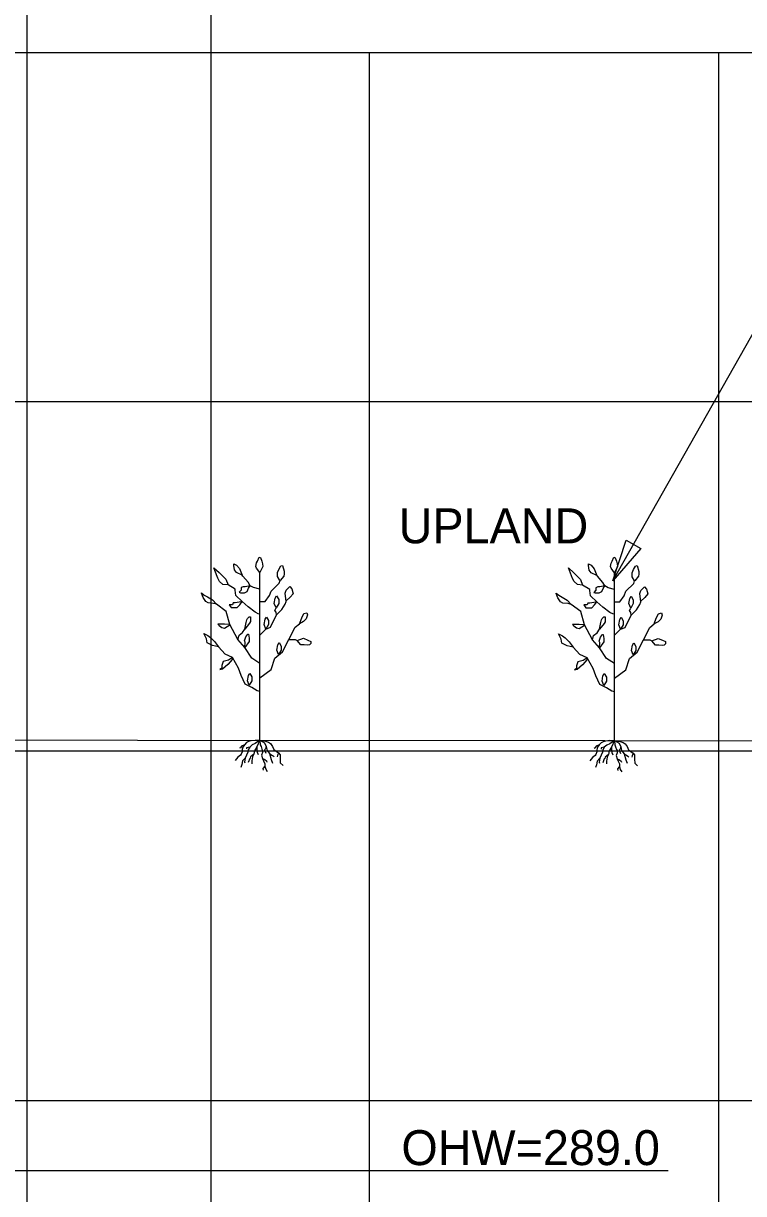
# Model space of a CAD drawing. Extents: x 1578769 to 1579225, y 724002 to 724828.
# Drawn here: x 1578825.08 to 1578835.39, y 724400.81 to 724417.56 of the extents above; entities that cross this region are included whole.
import ezdxf

# ---------------------------------------------------------------- set-up
doc = ezdxf.new("R2010")
doc.units = 0
for name, color, linetype in [('1', 7, 'Continuous'), ('Default', 7, 'Continuous'), ('Old_Level_1', 7, 'Continuous'), ('Old_Level_41', 7, 'Continuous'), ('R_Exist Surface', 7, 'Continuous')]:
    doc.layers.add(name, color=color, linetype=linetype)

msp = doc.modelspace()

# ---------------------------------------------------------------- linework, layer by layer
at = {"layer": '1'}
for p, q in [((1578828.465, 724407.303), (1578828.465, 724409.703)), ((1578833.539, 724407.3), (1578833.539, 724409.7)), ((1578828.47, 724407.298), (1578828.472, 724407.302)), ((1578833.544, 724407.295), (1578833.546, 724407.299)), ((1578820.032, 724401.146), (1578834.308, 724401.146))]:
    msp.add_line(p, q, dxfattribs=at)
for points in [[(1578833.517, 724409.582), (1578835.732, 724413.491), (1578836.418, 724413.491)], [(1578828.752, 724409.589), (1578828.721, 724409.646), (1578828.721, 724409.703), (1578828.74, 724409.747), (1578828.765, 724409.797), (1578828.79, 724409.804), (1578828.815, 724409.722), (1578828.815, 724409.684), (1578828.809, 724409.652), (1578828.759, 724409.589)], [(1578833.826, 724409.586), (1578833.795, 724409.643), (1578833.795, 724409.7), (1578833.814, 724409.744), (1578833.839, 724409.794), (1578833.864, 724409.801), (1578833.889, 724409.719), (1578833.889, 724409.681), (1578833.883, 724409.649), (1578833.833, 724409.586)], [(1578828.465, 724409.463), (1578828.377, 724409.488), (1578828.326, 724409.513), (1578828.301, 724409.564), (1578828.225, 724409.652), (1578828.213, 724409.665)], [(1578828.465, 724409.286), (1578828.541, 724409.286), (1578828.604, 724409.374), (1578828.629, 724409.437), (1578828.743, 724409.551), (1578828.755, 724409.589)], [(1578833.539, 724409.46), (1578833.451, 724409.485), (1578833.4, 724409.51), (1578833.375, 724409.561), (1578833.299, 724409.649), (1578833.287, 724409.662)], [(1578833.539, 724409.283), (1578833.615, 724409.283), (1578833.678, 724409.371), (1578833.703, 724409.434), (1578833.817, 724409.548), (1578833.829, 724409.586)], [(1578827.847, 724409.248), (1578827.803, 724409.261), (1578827.727, 724409.267), (1578827.695, 724409.286), (1578827.657, 724409.343), (1578827.632, 724409.406), (1578827.632, 724409.412), (1578827.67, 724409.381), (1578827.72, 724409.355), (1578827.79, 724409.311), (1578827.847, 724409.248)], [(1578828.453, 724409.109), (1578828.402, 724409.134), (1578828.301, 724409.21), (1578828.213, 724409.286), (1578828.124, 724409.374), (1578828.112, 724409.45), (1578828.112, 724409.463), (1578828.011, 724409.526)], [(1578828.699, 724409.197), (1578828.673, 724409.261), (1578828.686, 724409.336), (1578828.705, 724409.368), (1578828.737, 724409.317), (1578828.737, 724409.261), (1578828.699, 724409.197)], [(1578828.844, 724409.286), (1578828.831, 724409.406), (1578828.844, 724409.45), (1578828.894, 724409.501), (1578828.926, 724409.469), (1578828.945, 724409.4), (1578828.901, 724409.349), (1578828.844, 724409.298)], [(1578832.921, 724409.245), (1578832.876, 724409.258), (1578832.801, 724409.264), (1578832.769, 724409.283), (1578832.731, 724409.34), (1578832.706, 724409.403), (1578832.706, 724409.409), (1578832.744, 724409.378), (1578832.794, 724409.352), (1578832.864, 724409.308), (1578832.921, 724409.245)], [(1578833.526, 724409.106), (1578833.476, 724409.131), (1578833.375, 724409.207), (1578833.287, 724409.283), (1578833.198, 724409.371), (1578833.186, 724409.447), (1578833.186, 724409.46), (1578833.085, 724409.523)], [(1578833.773, 724409.194), (1578833.747, 724409.258), (1578833.76, 724409.333), (1578833.779, 724409.365), (1578833.81, 724409.314), (1578833.81, 724409.258), (1578833.773, 724409.194)], [(1578833.918, 724409.283), (1578833.905, 724409.403), (1578833.918, 724409.447), (1578833.968, 724409.498), (1578834, 724409.466), (1578834.019, 724409.397), (1578833.975, 724409.346), (1578833.918, 724409.295)], [(1578828.465, 724408.402), (1578828.352, 724408.477), (1578828.251, 724408.629), (1578828.15, 724408.743), (1578828.036, 724408.957), (1578827.986, 724409.147), (1578827.847, 724409.248)], [(1578828.465, 724408.818), (1578828.478, 724408.818), (1578828.554, 724408.894), (1578828.617, 724408.919), (1578828.705, 724409.096), (1578828.781, 724409.172), (1578828.831, 724409.248), (1578828.844, 724409.286)], [(1578828.705, 724409.096), (1578828.699, 724409.134), (1578828.68, 724409.159), (1578828.699, 724409.197)], [(1578833.539, 724408.399), (1578833.425, 724408.474), (1578833.324, 724408.626), (1578833.224, 724408.74), (1578833.11, 724408.954), (1578833.059, 724409.144), (1578832.921, 724409.245)], [(1578833.539, 724408.815), (1578833.552, 724408.815), (1578833.627, 724408.891), (1578833.691, 724408.917), (1578833.779, 724409.093), (1578833.855, 724409.169), (1578833.905, 724409.245), (1578833.918, 724409.283)], [(1578833.779, 724409.093), (1578833.773, 724409.131), (1578833.754, 724409.157), (1578833.773, 724409.194)], [(1578828.554, 724408.894), (1578828.528, 724408.957), (1578828.541, 724409.033), (1578828.56, 724409.065), (1578828.591, 724409.014), (1578828.591, 724408.957), (1578828.554, 724408.894)], [(1578829.033, 724408.97), (1578829.065, 724409.052), (1578829.096, 724409.115), (1578829.14, 724409.128), (1578829.147, 724409.096), (1578829.128, 724409.04), (1578829.09, 724409.002), (1578829.033, 724408.97)], [(1578833.627, 724408.891), (1578833.602, 724408.954), (1578833.615, 724409.03), (1578833.634, 724409.062), (1578833.665, 724409.011), (1578833.665, 724408.954), (1578833.627, 724408.891)], [(1578834.107, 724408.967), (1578834.139, 724409.049), (1578834.17, 724409.112), (1578834.214, 724409.125), (1578834.221, 724409.093), (1578834.202, 724409.037), (1578834.164, 724408.999), (1578834.107, 724408.967)], [(1578828.036, 724408.957), (1578827.962, 724408.964), (1578827.905, 724408.964), (1578827.866, 724408.964), (1578827.885, 724408.944), (1578827.924, 724408.916), (1578827.962, 724408.906), (1578828.038, 724408.954)], [(1578828.15, 724408.743), (1578828.169, 724408.806), (1578828.219, 724408.844), (1578828.251, 724408.894)], [(1578828.465, 724408.194), (1578828.629, 724408.313), (1578828.68, 724408.477), (1578828.793, 724408.566), (1578828.882, 724408.743), (1578828.97, 724408.919), (1578829.033, 724408.97)], [(1578833.11, 724408.954), (1578833.036, 724408.961), (1578832.978, 724408.961), (1578832.94, 724408.961), (1578832.959, 724408.941), (1578832.998, 724408.913), (1578833.036, 724408.903), (1578833.112, 724408.951)], [(1578833.224, 724408.74), (1578833.242, 724408.803), (1578833.293, 724408.841), (1578833.325, 724408.891)], [(1578833.539, 724408.191), (1578833.703, 724408.31), (1578833.754, 724408.474), (1578833.867, 724408.563), (1578833.956, 724408.74), (1578834.044, 724408.917), (1578834.107, 724408.967)], [(1578828.734, 724408.529), (1578828.709, 724408.592), (1578828.722, 724408.668), (1578828.741, 724408.699), (1578828.772, 724408.649), (1578828.772, 724408.592), (1578828.734, 724408.529)], [(1578828.882, 724408.743), (1578828.945, 724408.743), (1578828.97, 724408.743), (1578829.002, 724408.73)], [(1578829.002, 724408.73), (1578829.09, 724408.762), (1578829.153, 724408.736), (1578829.197, 724408.717), (1578829.197, 724408.686), (1578829.178, 724408.667), (1578829.147, 724408.661), (1578829.103, 724408.667), (1578829.052, 724408.667), (1578829.002, 724408.73)], [(1578833.808, 724408.526), (1578833.783, 724408.589), (1578833.796, 724408.665), (1578833.815, 724408.696), (1578833.846, 724408.646), (1578833.846, 724408.589), (1578833.808, 724408.526)], [(1578833.956, 724408.74), (1578834.019, 724408.74), (1578834.044, 724408.74), (1578834.076, 724408.727)], [(1578834.076, 724408.727), (1578834.164, 724408.759), (1578834.227, 724408.733), (1578834.271, 724408.714), (1578834.271, 724408.683), (1578834.252, 724408.664), (1578834.221, 724408.658), (1578834.177, 724408.664), (1578834.126, 724408.664), (1578834.076, 724408.727)], [(1578828.468, 724407.999), (1578828.43, 724408.008), (1578828.353, 724408.056), (1578828.258, 724408.104), (1578828.2, 724408.228), (1578828.162, 724408.333), (1578828.076, 724408.486), (1578827.971, 724408.534), (1578827.876, 724408.639), (1578827.876, 724408.639)], [(1578833.542, 724407.996), (1578833.504, 724408.005), (1578833.427, 724408.053), (1578833.332, 724408.101), (1578833.274, 724408.225), (1578833.236, 724408.33), (1578833.15, 724408.483), (1578833.045, 724408.531), (1578832.95, 724408.636), (1578832.95, 724408.636)], [(1578828.314, 724408.089), (1578828.289, 724408.152), (1578828.302, 724408.228), (1578828.321, 724408.26), (1578828.352, 724408.209), (1578828.352, 724408.152), (1578828.314, 724408.089)], [(1578833.388, 724408.086), (1578833.363, 724408.149), (1578833.376, 724408.225), (1578833.395, 724408.257), (1578833.426, 724408.206), (1578833.426, 724408.149), (1578833.388, 724408.086)], [(1578828.465, 724407.303), (1578828.414, 724407.297), (1578828.398, 724407.301), (1578828.34, 724407.293), (1578828.305, 724407.285), (1578828.278, 724407.27), (1578828.247, 724407.239), (1578828.224, 724407.204), (1578828.216, 724407.169), (1578828.216, 724407.138), (1578828.2, 724407.103), (1578828.189, 724407.087), (1578828.15, 724407.06), (1578828.115, 724407.013)], [(1578828.247, 724407.239), (1578828.204, 724407.219), (1578828.189, 724407.196), (1578828.177, 724407.188)], [(1578828.465, 724407.303), (1578828.398, 724407.254), (1578828.359, 724407.235), (1578828.321, 724407.204), (1578828.301, 724407.165), (1578828.293, 724407.134), (1578828.255, 724407.048), (1578828.22, 724407.006), (1578828.208, 724406.955), (1578828.193, 724406.913)], [(1578828.321, 724407.204), (1578828.278, 724407.196), (1578828.274, 724407.18)], [(1578828.465, 724407.303), (1578828.425, 724407.208), (1578828.39, 724407.153), (1578828.379, 724407.103), (1578828.363, 724407.064), (1578828.352, 724407.006), (1578828.352, 724406.967)], [(1578828.425, 724407.208), (1578828.425, 724407.153), (1578828.429, 724407.13), (1578828.441, 724407.099)], [(1578828.465, 724407.303), (1578828.549, 724407.287), (1578828.592, 724407.274), (1578828.619, 724407.254), (1578828.646, 724407.215), (1578828.666, 724407.169), (1578828.732, 724407.122), (1578828.755, 724407.095), (1578828.755, 724407.037), (1578828.759, 724406.979), (1578828.798, 724406.94)], [(1578828.465, 724407.303), (1578828.534, 724407.266), (1578828.557, 724407.211), (1578828.569, 724407.157), (1578828.604, 724407.111), (1578828.627, 724407.025), (1578828.65, 724406.975)], [(1578828.465, 724407.303), (1578828.472, 724407.239), (1578828.484, 724407.211), (1578828.495, 724407.173), (1578828.503, 724407.157), (1578828.503, 724407.126), (1578828.491, 724407.087), (1578828.503, 724407.041), (1578828.518, 724407.006), (1578828.538, 724406.967), (1578828.538, 724406.932), (1578828.55, 724406.889), (1578828.573, 724406.854)], [(1578828.557, 724407.211), (1578828.546, 724407.18), (1578828.534, 724407.165), (1578828.553, 724407.118)], [(1578833.539, 724407.3), (1578833.488, 724407.294), (1578833.472, 724407.298), (1578833.414, 724407.29), (1578833.379, 724407.282), (1578833.352, 724407.267), (1578833.321, 724407.236), (1578833.298, 724407.201), (1578833.29, 724407.166), (1578833.29, 724407.135), (1578833.274, 724407.1), (1578833.263, 724407.084), (1578833.224, 724407.057), (1578833.189, 724407.01)], [(1578833.321, 724407.236), (1578833.278, 724407.216), (1578833.263, 724407.193), (1578833.251, 724407.185)], [(1578833.539, 724407.3), (1578833.472, 724407.251), (1578833.433, 724407.232), (1578833.395, 724407.201), (1578833.375, 724407.162), (1578833.367, 724407.131), (1578833.329, 724407.045), (1578833.294, 724407.003), (1578833.282, 724406.952), (1578833.267, 724406.91)], [(1578833.395, 724407.201), (1578833.352, 724407.193), (1578833.348, 724407.177)], [(1578833.539, 724407.3), (1578833.499, 724407.205), (1578833.464, 724407.15), (1578833.453, 724407.1), (1578833.437, 724407.061), (1578833.426, 724407.003), (1578833.426, 724406.964)], [(1578833.499, 724407.205), (1578833.499, 724407.15), (1578833.503, 724407.127), (1578833.515, 724407.096)], [(1578833.539, 724407.3), (1578833.623, 724407.284), (1578833.666, 724407.271), (1578833.693, 724407.251), (1578833.72, 724407.212), (1578833.74, 724407.166), (1578833.806, 724407.119), (1578833.829, 724407.092), (1578833.829, 724407.034), (1578833.833, 724406.976), (1578833.872, 724406.937)], [(1578833.539, 724407.3), (1578833.608, 724407.263), (1578833.631, 724407.208), (1578833.643, 724407.154), (1578833.678, 724407.108), (1578833.701, 724407.022), (1578833.724, 724406.972)], [(1578833.539, 724407.3), (1578833.546, 724407.236), (1578833.557, 724407.208), (1578833.569, 724407.17), (1578833.577, 724407.154), (1578833.577, 724407.123), (1578833.565, 724407.084), (1578833.577, 724407.038), (1578833.592, 724407.003), (1578833.612, 724406.964), (1578833.612, 724406.929), (1578833.623, 724406.886), (1578833.647, 724406.851)], [(1578833.631, 724407.208), (1578833.62, 724407.177), (1578833.608, 724407.162), (1578833.627, 724407.115)], [(1578828.255, 724407.048), (1578828.247, 724406.994), (1578828.251, 724406.979)], [(1578828.379, 724407.103), (1578828.332, 724407.064), (1578828.328, 724407.045), (1578828.321, 724407.041), (1578828.301, 724406.982)], [(1578828.503, 724407.041), (1578828.538, 724407.025), (1578828.561, 724407.006), (1578828.565, 724406.99)], [(1578828.604, 724407.111), (1578828.639, 724407.091), (1578828.658, 724407.079), (1578828.67, 724407.068)], [(1578828.732, 724407.122), (1578828.72, 724407.083), (1578828.716, 724407.064)], [(1578833.329, 724407.045), (1578833.321, 724406.991), (1578833.325, 724406.976)], [(1578833.453, 724407.1), (1578833.406, 724407.061), (1578833.402, 724407.042), (1578833.395, 724407.038), (1578833.375, 724406.979)], [(1578833.577, 724407.038), (1578833.612, 724407.022), (1578833.635, 724407.003), (1578833.639, 724406.987)], [(1578833.678, 724407.108), (1578833.713, 724407.088), (1578833.732, 724407.076), (1578833.744, 724407.065)], [(1578833.806, 724407.119), (1578833.794, 724407.08), (1578833.79, 724407.061)], [(1578828.538, 724406.932), (1578828.511, 724406.897), (1578828.515, 724406.874)], [(1578833.612, 724406.929), (1578833.585, 724406.894), (1578833.589, 724406.871)]]:
    msp.add_lwpolyline(points, dxfattribs=at)
for points in [[(1578833.917, 724410.045), (1578833.517, 724409.582), (1578833.708, 724410.164)], [(1578828.465, 724409.703), (1578828.421, 724409.766), (1578828.408, 724409.791), (1578828.421, 724409.842), (1578828.434, 724409.867), (1578828.459, 724409.924), (1578828.478, 724409.917), (1578828.497, 724409.867), (1578828.503, 724409.829), (1578828.509, 724409.791)], [(1578833.539, 724409.7), (1578833.495, 724409.763), (1578833.482, 724409.788), (1578833.495, 724409.839), (1578833.508, 724409.864), (1578833.533, 724409.921), (1578833.552, 724409.914), (1578833.571, 724409.864), (1578833.577, 724409.826), (1578833.583, 724409.788)], [(1578828.011, 724409.526), (1578827.935, 724409.532), (1578827.891, 724409.576), (1578827.866, 724409.621), (1578827.821, 724409.734), (1578827.809, 724409.772), (1578827.885, 724409.703), (1578827.929, 724409.658), (1578827.979, 724409.608)], [(1578828.213, 724409.665), (1578828.131, 724409.703), (1578828.105, 724409.741), (1578828.093, 724409.804), (1578828.093, 724409.829), (1578828.131, 724409.81), (1578828.175, 724409.76)], [(1578833.085, 724409.523), (1578833.009, 724409.529), (1578832.965, 724409.573), (1578832.94, 724409.618), (1578832.895, 724409.731), (1578832.883, 724409.769), (1578832.958, 724409.7), (1578833.003, 724409.655), (1578833.053, 724409.605)], [(1578833.287, 724409.662), (1578833.205, 724409.7), (1578833.179, 724409.738), (1578833.167, 724409.801), (1578833.167, 724409.826), (1578833.205, 724409.807), (1578833.249, 724409.757)], [(1578828.326, 724409.513), (1578828.258, 724409.499), (1578828.229, 724409.499), (1578828.2, 724409.489), (1578828.2, 724409.451), (1578828.172, 724409.422), (1578828.191, 724409.413), (1578828.248, 724409.413), (1578828.286, 724409.432), (1578828.305, 724409.479)], [(1578833.4, 724409.51), (1578833.332, 724409.496), (1578833.303, 724409.496), (1578833.274, 724409.486), (1578833.274, 724409.448), (1578833.246, 724409.419), (1578833.265, 724409.41), (1578833.322, 724409.41), (1578833.36, 724409.429), (1578833.379, 724409.476)], [(1578828.213, 724409.286), (1578828.172, 724409.279), (1578828.115, 724409.269), (1578828.086, 724409.269), (1578828.076, 724409.241), (1578828.029, 724409.241), (1578828.057, 724409.202), (1578828.095, 724409.202), (1578828.143, 724409.202), (1578828.181, 724409.241)], [(1578833.287, 724409.283), (1578833.246, 724409.276), (1578833.188, 724409.266), (1578833.16, 724409.266), (1578833.15, 724409.238), (1578833.103, 724409.238), (1578833.131, 724409.199), (1578833.169, 724409.199), (1578833.217, 724409.199), (1578833.255, 724409.238)], [(1578828.251, 724408.894), (1578828.27, 724408.989), (1578828.282, 724409.027), (1578828.288, 724409.046), (1578828.314, 724409.071), (1578828.333, 724409.071), (1578828.333, 724409.002), (1578828.32, 724408.976)], [(1578833.325, 724408.891), (1578833.343, 724408.986), (1578833.356, 724409.024), (1578833.362, 724409.043), (1578833.388, 724409.068), (1578833.407, 724409.068), (1578833.407, 724408.999), (1578833.394, 724408.973)], [(1578827.876, 724408.639), (1578827.79, 724408.658), (1578827.714, 724408.696), (1578827.704, 724408.753), (1578827.666, 724408.83), (1578827.723, 724408.801), (1578827.761, 724408.772), (1578827.819, 724408.715), (1578827.847, 724408.677)], [(1578828.251, 724408.629), (1578828.258, 724408.706), (1578828.248, 724408.725), (1578828.267, 724408.782), (1578828.296, 724408.82), (1578828.305, 724408.82), (1578828.315, 724408.763), (1578828.315, 724408.715)], [(1578832.95, 724408.636), (1578832.864, 724408.655), (1578832.788, 724408.693), (1578832.778, 724408.75), (1578832.74, 724408.827), (1578832.797, 724408.798), (1578832.835, 724408.769), (1578832.893, 724408.712), (1578832.921, 724408.674)], [(1578833.324, 724408.626), (1578833.332, 724408.703), (1578833.322, 724408.722), (1578833.341, 724408.779), (1578833.37, 724408.817), (1578833.379, 724408.817), (1578833.389, 724408.76), (1578833.389, 724408.712)], [(1578828.076, 724408.486), (1578828.019, 724408.448), (1578827.943, 724408.429), (1578827.924, 724408.371), (1578827.924, 724408.333), (1578827.895, 724408.314), (1578827.933, 724408.323), (1578828.01, 724408.39), (1578828.019, 724408.39), (1578828.076, 724408.457)], [(1578833.15, 724408.483), (1578833.093, 724408.445), (1578833.017, 724408.426), (1578832.998, 724408.368), (1578832.998, 724408.33), (1578832.969, 724408.311), (1578833.007, 724408.32), (1578833.083, 724408.387), (1578833.093, 724408.387), (1578833.15, 724408.454)]]:
    msp.add_lwpolyline(points, close=True, dxfattribs=at)
at = {"layer": 'Default'}
for p, q in [((1578827.766, 724526.976), (1578827.766, 724276.976)), ((1578825.136, 724252.141), (1578825.136, 724502.141))]:
    msp.add_line(p, q, dxfattribs=at)
at = {"layer": 'Old_Level_1'}
msp.add_lwpolyline([(1578820.032, 724417.146), (1578940.032, 724417.146), (1578940.032, 724387.146), (1578820.032, 724387.146)], dxfattribs=at)
at = {"layer": 'Old_Level_41'}
for p, q in [((1578830.032, 724417.146), (1578830.032, 724387.146)), ((1578835.032, 724387.146), (1578835.032, 724417.146))]:
    msp.add_line(p, q, dxfattribs=at)
for points in [[(1578940.032, 724412.146), (1578820.032, 724412.146)], [(1578940.032, 724407.146), (1578820.032, 724407.146)], [(1578820.032, 724402.146), (1578940.032, 724402.146)]]:
    msp.add_lwpolyline(points, dxfattribs=at)
at = {"layer": 'R_Exist Surface'}
msp.add_lwpolyline([(1578820.032, 724407.308), (1578840.086, 724407.296), (1578856.158, 724407.113), (1578866.051, 724406.984), (1578870.101, 724406.953), (1578871.119, 724406.484), (1578874.093, 724402.856), (1578881.072, 724394.627), (1578882.067, 724394.215), (1578883.085, 724394.135), (1578888.061, 724393.7), (1578893.092, 724393.289), (1578898.075, 724392.849), (1578907.062, 724392.008), (1578915.073, 724391.301), (1578925.131, 724390.401), (1578931.075, 724391.042), (1578938.041, 724391.763), (1578940.032, 724391.965)], dxfattribs=at)

# ---------------------------------------------------------------- texts
at = {"layer": '1'}
for s, p in [('UPLAND', (1578830.453, 724410.121)), ('OHW=289.0', (1578830.492, 724401.222))]:
    msp.add_text(s, height=0.5, dxfattribs=at).set_placement(p)

doc.saveas('drawing.dxf')
